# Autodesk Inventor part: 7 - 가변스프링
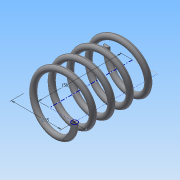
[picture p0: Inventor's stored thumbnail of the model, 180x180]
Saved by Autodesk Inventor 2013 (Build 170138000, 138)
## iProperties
Created: 2015-03
Part Number: 7 - 가변스프링
Material: 강철, 탄소
Document SubType Name: Modeling
Designer: Administrator
Density: 7.87 g/cm^3
Mass: 47.9935 g
Surface Area: 62.0176 cm^2
Volume: 6.09829 cm^3
Author: Administrator
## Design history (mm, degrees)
sketch "스케치1"
  geometry: L1 (0, 0)-(17.5, 0); L2 (17.5, 0)-(17.5, 43.5); L3 (17.5, 43.5)-(0, 43.5); L4 (0, 43.5)-(0, 0); C1 r 2 at (17.5, 0)
  constraints: 8 end point, 2 parallel, 1 centre point, 1 coincident, 1 horizontal, 1 perpendicular
  dimensions: "d0" = 4 diameter of C1; "d2" = 35 diameter of L2 L4; "d3" = 43.5 distance of L3.end L1.start (derived)
feature "코일1" sketch "스케치1" pitch "d4" = 10; turns "d6" = 4.5; dims "d5" = 43.5 (= d3), "d7" = 0, angle "d8" = 90 deg, angle "d9" = 90 deg, "d10" = 0, "d11" = 0
node "작업 평면1"
sketch "스케치2"
  geometry: L1 (-19.5, 0)-(-15.5, 0) reference; 1 further point
  constraints: 1 horizontal alignment
extrude "돌출1" cut sketch "스케치2" stored distance "d13" = 10; taper "d14" = 0 deg
sketch "스케치3"
  geometry: L1 (15.5, 0)-(19.5, 0) reference; 1 further point
  constraints: 1 horizontal alignment
extrude "돌출2" cut sketch "스케치3" stored distance "d15" = 10; taper "d16" = 0 deg
node "솔리드1"
node "절단 모서리 투영1"
node "절단 모서리 투영2"
other parameters: "d12" = 43.5 (= d3)
